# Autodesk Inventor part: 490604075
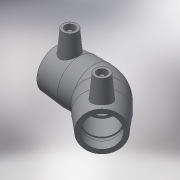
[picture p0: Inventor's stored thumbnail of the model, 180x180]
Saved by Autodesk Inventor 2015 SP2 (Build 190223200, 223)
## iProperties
Created: 2017-06
Part Number: 490604075
Material: Generic
Description: PLASSON 45° ELBOW 75
Document SubType Name: Modeling
Designer: KIM
Mass: 55.0731 g
Surface Area: 148.067 cm^2
Volume: 55.0731 cm^3
Density: 1 g/cm^3
Appearance: Default
Author: KIM
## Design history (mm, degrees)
derived "490604.ipt"
feature "Solid1::490604.ipt"
tag "TaggingFeature1"
body "Solid1"
other parameters: "d2" = 96, "d4" = 45, "d5" = 86.4, "d8" = 168 deg, "d10" = 28.4, "d11" = 9.46667, "d14" = 17.6296, "d18" = 75, "d19" = 3.52592, "d20" = 168 deg, "d22" = 88.32, "d23" = 96, "d24" = 85.6704, "d29" = 62, "d30" = 15, "d31" = 72, "d34" = 5 deg, "d35" = 12, "d39" = 0, "d41" = 4, "d42" = 14, "d43" = 0, "d44" = 9.6, "d45" = 4.8, "d46" = 6, "d47" = 0, "d49" = 75, "d50" = 63.75, "d51" = 28.4, "d52" = 71, "d54" = 135 deg, "d65" = 75, "d67" = 45 deg, "d71" = 135 deg, "d75" = 4.8, "d82" = 45 deg, "d83" = 71, "d84" = 86.4, "d86" = 43.2, "d87" = 135 deg, "d90" = 71, "d91" = 0, "d92" = 71, "d93" = 0, "d94" = 135 deg, "d95" = 44.16, "d99" = 54, "d101" = 3, "d102" = 0, "d103" = 3, "d104" = 0, "d105" = 20.59, "d106" = 5.1475, "d_" = 75, "L_1" = 71, "D_" = 96, "A_" = 62, "d_2" = 12
